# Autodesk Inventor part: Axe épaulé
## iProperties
Author: Flavien MARTY
Shininess: 60.0
PropertySet Name: _Private Model Information
Created: 2001-10
Part Number: Axe épaulé
Material: Par défaut
Document SubType Name: Modélisation
Designer: Flavien MARTY
Control State: 0
Master: False
Checked Out: False
PropertySet Name: Design Tracking Control
Density: 0.0
Volumn: 0.0
Area: 0.0
PropertySet Name: Model Information
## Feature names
1. Base1
